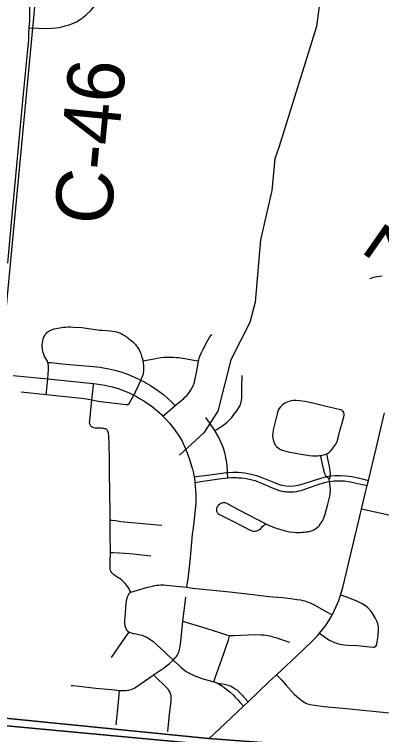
# Model space of a CAD drawing. Extents: x 0 to 34, y 0 to 22.
# Drawn here: x 22.884 to 23.251, y 14.925 to 15.645 of the extents above; entities that cross this region are included whole.
import ezdxf

# ---------------------------------------------------------------- set-up
doc = ezdxf.new("R2010")
doc.units = 0
for name, color, linetype in [('GM_X_City_Street', 7, 'Continuous'), ('GM_X_County_Road', 7, 'Continuous'), ('GM_X_County_Road_Text', 7, 'Continuous'), ('GM_X_Minor_River', 7, 'Continuous'), ('GM_X_Section', 7, 'Continuous'), ('GM_X_Township_Road', 7, 'Continuous'), ('SH_Border', 7, 'Continuous')]:
    doc.layers.add(name, color=color, linetype=linetype)

msp = doc.modelspace()

# ---------------------------------------------------------------- linework, layer by layer
at = {"layer": 'GM_X_City_Street'}
for p, q in [((22.89059, 15.26813), (22.91581, 15.26543)), ((23.19877, 15.17844), (23.19831, 15.18065)), ((23.0832, 14.97792), (23.0861, 14.97706))]:
    msp.add_line(p, q, dxfattribs=at)
for points in [[(22.91735, 15.29732), (22.91685, 15.29851), (22.91479, 15.30222), (22.91417, 15.30347), (22.91335, 15.30539), (22.91271, 15.30722), (22.91236, 15.30861), (22.91203, 15.31023), (22.9119, 15.31123), (22.9118, 15.31314), (22.91184, 15.31506), (22.91198, 15.31712), (22.91224, 15.31904), (22.91274, 15.32094), (22.91343, 15.32281), (22.91389, 15.32371), (22.91482, 15.32528), (22.91541, 15.32608), (22.916, 15.3268), (22.91673, 15.32749), (22.91746, 15.32805), (22.91833, 15.3287), (22.91927, 15.32924), (22.92084, 15.32994), (22.92187, 15.33034), (22.92288, 15.33069), (22.92353, 15.33088), (22.92558, 15.33137), (22.93115, 15.33237), (22.93253, 15.33253), (22.93405, 15.33266), (22.93524, 15.33275), (22.9374, 15.33284), (22.94042, 15.33286), (22.94255, 15.33279), (22.9512, 15.33216), (22.95793, 15.33131), (22.96921, 15.32978), (22.97153, 15.32954), (22.97996, 15.32888), (22.98168, 15.32867), (22.98424, 15.32826), (22.98596, 15.32786), (22.98797, 15.32729), (22.98918, 15.32683), (22.99046, 15.32626), (22.99194, 15.32547), (22.99343, 15.32457), (22.99458, 15.32383), (22.99525, 15.32338), (22.99644, 15.32254), (22.99745, 15.32181), (22.99924, 15.32045), (23.00028, 15.31961), (23.00218, 15.31795), (23.00357, 15.31661), (23.00474, 15.31534), (23.00605, 15.31373), (23.00676, 15.31277), (23.00789, 15.31109), (23.0086, 15.30985), (23.00966, 15.30771), (23.01022, 15.30628), (23.01104, 15.30376), (23.01209, 15.29997), (23.01227, 15.29884)], [(23.06785, 15.29885), (23.06812, 15.30006), (23.06887, 15.30269), (23.0695, 15.3044), (23.07039, 15.3065), (23.07184, 15.30946), (23.07637, 15.31815), (23.07919, 15.32302), (23.08069, 15.32512), (23.08113, 15.32562)], [(23.01227, 15.29884), (23.01772, 15.29995), (23.02339, 15.30112), (23.02653, 15.30166), (23.03011, 15.30216), (23.03336, 15.3025), (23.03586, 15.30267), (23.03895, 15.30274), (23.0428, 15.30267), (23.0454, 15.30246), (23.04814, 15.30218), (23.05037, 15.30185), (23.06301, 15.29968), (23.06785, 15.29885)], [(22.91719, 15.28104), (22.91785, 15.29033), (22.91792, 15.2915), (22.91796, 15.29337), (22.91792, 15.29448), (22.91784, 15.29547), (22.91769, 15.29618), (22.91735, 15.29732)], [(22.91735, 15.29732), (22.91833, 15.29728), (22.9203, 15.29717), (22.93515, 15.29549), (22.96294, 15.29316), (22.96977, 15.29252), (22.97462, 15.29178), (22.97673, 15.29136), (22.98303, 15.2899), (22.98543, 15.28927), (22.99111, 15.2876), (22.9934, 15.28684), (22.99774, 15.28523), (22.99979, 15.28439), (23.00763, 15.28096), (23.00909, 15.28026), (23.01016, 15.27971)], [(23.01227, 15.29884), (23.01265, 15.29664), (23.01286, 15.29463), (23.01293, 15.29339), (23.01293, 15.29098), (23.01283, 15.28904), (23.01259, 15.28695), (23.01239, 15.28582), (23.01194, 15.2841), (23.01153, 15.28285), (23.01129, 15.28224), (23.0107, 15.28087), (23.01016, 15.27971)], [(23.04455, 15.25417), (23.05299, 15.26135), (23.05461, 15.26289), (23.05645, 15.2648), (23.05768, 15.26623), (23.0587, 15.26754), (23.05985, 15.2692), (23.06061, 15.27046), (23.06161, 15.27235), (23.06267, 15.27481), (23.06372, 15.27778), (23.06426, 15.27963), (23.0656, 15.28526), (23.06689, 15.29252), (23.06785, 15.29885)], [(22.88285, 15.28427), (22.91719, 15.28104), (22.94959, 15.27764), (22.96308, 15.27617), (22.96568, 15.27588), (22.97433, 15.27453), (22.98167, 15.27293), (22.9877, 15.27121), (22.99362, 15.2691), (22.99855, 15.26695), (23.00057, 15.26597), (23.00315, 15.26464), (23.00599, 15.26317), (23.00904, 15.26145), (23.01313, 15.25903), (23.01568, 15.25734), (23.02008, 15.25425), (23.02394, 15.2513), (23.02622, 15.24938), (23.03083, 15.24524), (23.0323, 15.24374), (23.03565, 15.24032), (23.0389, 15.23657), (23.04133, 15.2336), (23.04393, 15.23021), (23.04599, 15.22728), (23.04769, 15.22474), (23.04944, 15.22192), (23.0514, 15.21853), (23.0539, 15.21346), (23.05653, 15.20709), (23.05924, 15.19943), (23.06127, 15.19258), (23.06182, 15.1906), (23.06246, 15.18799), (23.06318, 15.1847), (23.0635, 15.18299), (23.06387, 15.18105), (23.06441, 15.17747)], [(22.91581, 15.26543), (22.91602, 15.26782), (22.91719, 15.28104)], [(23.084, 15.22933), (23.08605, 15.23047), (23.08793, 15.23152), (23.0892, 15.2323), (23.09116, 15.2336), (23.09475, 15.23633), (23.09627, 15.23759), (23.09766, 15.23887), (23.09917, 15.24041), (23.10096, 15.24243), (23.10248, 15.24427), (23.10481, 15.24727), (23.10608, 15.24901), (23.10773, 15.25153), (23.1087, 15.2532), (23.10927, 15.25436), (23.10983, 15.25571), (23.11015, 15.25667), (23.11034, 15.25741), (23.11057, 15.25853), (23.11069, 15.25924), (23.11094, 15.26212), (23.11123, 15.2724), (23.11155, 15.28423)], [(22.96138, 15.2599), (22.96199, 15.26565), (22.96285, 15.2743), (22.96308, 15.27617)], [(23.01016, 15.27971), (23.00458, 15.26772), (23.00315, 15.26464)], [(23.01016, 15.27971), (23.01312, 15.27818), (23.01531, 15.27693), (23.01984, 15.2742), (23.02811, 15.26865), (23.03313, 15.26493), (23.03696, 15.26168), (23.04096, 15.25792), (23.04263, 15.25617), (23.04455, 15.25417)], [(22.91581, 15.26543), (22.95097, 15.26167), (22.95376, 15.26132), (22.95611, 15.2609), (22.96138, 15.2599)], [(22.95915, 15.23884), (22.96033, 15.2499), (22.96138, 15.2599)], [(22.96138, 15.2599), (22.96596, 15.25903), (22.96781, 15.25873), (22.96984, 15.25846), (22.99571, 15.2552), (22.99665, 15.25525), (22.99736, 15.25547), (22.99844, 15.25635), (23.00315, 15.26464)], [(23.19598, 15.20606), (23.197, 15.20658), (23.19763, 15.20693), (23.19858, 15.20762), (23.19932, 15.20836), (23.19993, 15.2091), (23.20307, 15.21296), (23.2048, 15.21553), (23.20617, 15.21832), (23.2073, 15.22187), (23.2091, 15.2291), (23.21078, 15.23572), (23.21282, 15.24289), (23.21319, 15.24472), (23.21319, 15.24596), (23.21284, 15.24717), (23.2122, 15.24829), (23.21132, 15.24922), (23.2108, 15.2496), (23.20965, 15.25002), (23.19278, 15.25411), (23.18191, 15.25663), (23.17401, 15.25818), (23.16914, 15.25914), (23.16542, 15.2594), (23.16232, 15.25927), (23.15926, 15.25873), (23.1569, 15.25796), (23.15412, 15.25659), (23.15156, 15.25483), (23.14973, 15.25315), (23.14821, 15.25118), (23.14737, 15.24952), (23.14638, 15.24594), (23.14277, 15.23147), (23.14197, 15.22719), (23.14182, 15.22471), (23.14205, 15.22161), (23.14269, 15.21856), (23.14355, 15.21624), (23.14452, 15.21465), (23.14573, 15.21325), (23.14765, 15.21167), (23.1498, 15.21043), (23.15269, 15.2093), (23.15749, 15.20801), (23.17031, 15.20565), (23.17827, 15.20431), (23.18198, 15.20398), (23.18519, 15.20394), (23.18639, 15.20398), (23.1885, 15.20417), (23.18986, 15.20437)], [(23.0323, 15.24374), (23.03418, 15.24533), (23.04455, 15.25417)], [(22.97953, 15.13978), (22.97945, 15.14593), (22.9792, 15.16766), (22.97904, 15.18693), (22.97891, 15.1987), (22.97851, 15.21811), (22.97842, 15.22057), (22.9783, 15.22308), (22.97817, 15.2247), (22.97804, 15.22592), (22.97794, 15.22662), (22.97763, 15.22781), (22.97725, 15.22874), (22.97689, 15.22932), (22.97594, 15.2303), (22.97488, 15.23084), (22.97423, 15.23106), (22.97331, 15.23128), (22.97205, 15.23145), (22.97065, 15.23155), (22.96825, 15.23158), (22.96452, 15.23181), (22.96327, 15.232), (22.96228, 15.23224), (22.96158, 15.23256), (22.96102, 15.23292), (22.96041, 15.23353), (22.9599, 15.23429), (22.95962, 15.23485), (22.95926, 15.23608), (22.95912, 15.23744), (22.95915, 15.23884)], [(23.09716, 15.18204), (23.0968, 15.18734), (23.09629, 15.19485), (23.09576, 15.19888), (23.0952, 15.20216), (23.09472, 15.20449), (23.0941, 15.20703), (23.09268, 15.21182), (23.0911, 15.21579), (23.08992, 15.21855), (23.08768, 15.22316), (23.08454, 15.22851), (23.084, 15.22933), (23.0798, 15.2358), (23.07507, 15.24235)], [(23.18986, 15.20437), (23.19052, 15.20446), (23.19146, 15.20464), (23.19271, 15.20494), (23.19391, 15.20529), (23.19598, 15.20606)], [(23.19552, 15.18323), (23.19475, 15.18445), (23.19419, 15.18569), (23.1937, 15.18714), (23.19326, 15.18872), (23.19278, 15.19106), (23.19038, 15.20184), (23.19003, 15.20354), (23.18986, 15.20437)], [(23.19958, 15.18394), (23.19969, 15.18509), (23.19963, 15.1867), (23.19942, 15.18837), (23.19884, 15.19156), (23.19657, 15.20278), (23.19621, 15.20477), (23.19598, 15.20606)], [(23.0635, 15.18299), (23.06548, 15.18327), (23.06759, 15.18358), (23.07419, 15.18442), (23.0865, 15.18613), (23.09575, 15.18728), (23.0968, 15.18734), (23.10196, 15.18764), (23.10755, 15.18754), (23.11372, 15.18686), (23.12044, 15.18558), (23.12586, 15.1842), (23.13117, 15.18243), (23.14088, 15.1783), (23.14668, 15.17602), (23.15085, 15.17479), (23.15511, 15.174), (23.15883, 15.17373), (23.16317, 15.17392), (23.16746, 15.17465), (23.17226, 15.17592), (23.18053, 15.17866), (23.18995, 15.1818), (23.19474, 15.18309), (23.19552, 15.18323), (23.19958, 15.18394), (23.20393, 15.18441), (23.2095, 15.18448), (23.21506, 15.18414), (23.22118, 15.1833), (23.22845, 15.18177), (23.23122, 15.18106), (23.2375, 15.17945)], [(23.06441, 15.17747), (23.07222, 15.17866), (23.09075, 15.18133), (23.09453, 15.18178), (23.09716, 15.18204), (23.10069, 15.18223), (23.1039, 15.18226), (23.10591, 15.18227), (23.10791, 15.18217), (23.11091, 15.18191), (23.11353, 15.18157), (23.11707, 15.18093), (23.12123, 15.17993), (23.12393, 15.1792), (23.12671, 15.17831), (23.12836, 15.17767), (23.13547, 15.17455), (23.14233, 15.17162), (23.1476, 15.16975), (23.15111, 15.16881), (23.15261, 15.16849), (23.15419, 15.16823), (23.15575, 15.16805), (23.15828, 15.1679), (23.15943, 15.16791), (23.16173, 15.16799), (23.16317, 15.16814), (23.16571, 15.16848), (23.16785, 15.16891), (23.17029, 15.1695), (23.17244, 15.17013), (23.17849, 15.17227), (23.18728, 15.17539), (23.19369, 15.17729), (23.19614, 15.17795), (23.19877, 15.17844), (23.20295, 15.17894), (23.20528, 15.17907), (23.20805, 15.17911), (23.21074, 15.17907), (23.21345, 15.17884), (23.21739, 15.17834), (23.21961, 15.17796), (23.22381, 15.17709), (23.23004, 15.17577), (23.23626, 15.17446)], [(23.19831, 15.18065), (23.19648, 15.18223), (23.19601, 15.18267), (23.19552, 15.18323)], [(23.19831, 15.18065), (23.19916, 15.18246), (23.19958, 15.18394)], [(23.05623, 15.07258), (23.05657, 15.0752), (23.05734, 15.08106), (23.05878, 15.09266), (23.05947, 15.09883), (23.06041, 15.10993), (23.06185, 15.12529), (23.06267, 15.132), (23.06342, 15.13787), (23.06415, 15.14368), (23.06511, 15.15337), (23.06541, 15.15706), (23.0655, 15.15957), (23.06551, 15.16351), (23.06542, 15.16629), (23.06522, 15.16928), (23.06441, 15.17747)], [(23.13519, 15.13535), (23.13427, 15.1351), (23.13363, 15.13481), (23.13255, 15.134), (23.13088, 15.13251), (23.12897, 15.13046), (23.1281, 15.12972), (23.12728, 15.12918), (23.12662, 15.12885), (23.12577, 15.12857), (23.12431, 15.12834), (23.12336, 15.12837), (23.12268, 15.12848), (23.1215, 15.1288), (23.12062, 15.12909), (23.11853, 15.13003), (23.11769, 15.13046), (23.11484, 15.132), (23.10041, 15.13933), (23.09056, 15.1442), (23.08919, 15.14495), (23.08851, 15.14539), (23.08793, 15.1458), (23.08729, 15.14634), (23.08679, 15.14697), (23.08643, 15.14762), (23.08613, 15.14844), (23.08596, 15.14951), (23.08593, 15.1502), (23.08599, 15.15086), (23.0862, 15.15182), (23.08647, 15.15255), (23.08679, 15.15323), (23.08733, 15.15402), (23.08802, 15.15489), (23.08862, 15.15552), (23.08976, 15.15641), (23.09085, 15.15703), (23.09198, 15.15731), (23.09298, 15.15735), (23.09362, 15.1573), (23.09426, 15.15722), (23.09512, 15.15704), (23.0966, 15.15647), (23.09777, 15.15583), (23.10084, 15.15406), (23.10683, 15.15065), (23.11789, 15.14491), (23.12663, 15.14025), (23.13491, 15.13585), (23.14008, 15.13358), (23.14547, 15.13164), (23.14883, 15.13059), (23.15325, 15.12933), (23.15876, 15.12812), (23.16276, 15.12761), (23.16503, 15.12744), (23.16727, 15.12742), (23.16964, 15.12749), (23.17145, 15.12759), (23.17319, 15.12771), (23.17495, 15.12786), (23.17651, 15.12806), (23.1777, 15.12824), (23.17872, 15.12843), (23.17953, 15.12862), (23.18125, 15.12919), (23.18232, 15.12964), (23.18312, 15.13006), (23.18404, 15.13057), (23.18469, 15.13098), (23.18545, 15.13152), (23.18647, 15.13234), (23.18717, 15.13298), (23.1878, 15.13363), (23.18854, 15.13449), (23.1891, 15.1352), (23.19025, 15.13685), (23.1912, 15.13834), (23.1919, 15.13965), (23.19258, 15.14098), (23.19301, 15.14191), (23.19345, 15.14304), (23.19397, 15.14453), (23.19478, 15.14716), (23.19692, 15.15566), (23.1988, 15.16375), (23.19918, 15.16553), (23.19942, 15.16696), (23.1996, 15.16854), (23.1996, 15.17079), (23.19877, 15.17844)], [(23.27293, 15.14127), (23.24437, 15.14754), (23.23061, 15.15057)], [(22.97977, 15.1074), (22.97973, 15.12668), (22.97953, 15.13978)], [(22.97953, 15.13978), (22.98024, 15.13976), (22.98152, 15.13972), (22.98499, 15.13926), (22.9904, 15.13845), (23.00482, 15.13692), (23.02698, 15.13489), (23.03129, 15.13452)], [(23.00026, 15.06779), (22.99938, 15.0695), (22.99885, 15.07046), (22.99852, 15.07104), (22.9979, 15.07202), (22.99695, 15.07344), (22.99629, 15.07433), (22.99468, 15.0763), (22.99392, 15.07712), (22.9923, 15.07872), (22.99126, 15.07962), (22.98956, 15.08091), (22.98824, 15.08181), (22.98415, 15.08433), (22.98325, 15.08495), (22.98247, 15.08558), (22.98171, 15.08631), (22.98113, 15.08697), (22.98068, 15.08767), (22.98017, 15.08874), (22.97996, 15.08933), (22.97963, 15.09066), (22.97947, 15.09268), (22.97952, 15.09532), (22.97961, 15.09845), (22.97977, 15.1074)], [(22.97977, 15.1074), (22.98244, 15.10732), (22.98901, 15.10709), (22.9944, 15.10673), (23.00245, 15.10614), (23.02025, 15.10414)], [(23.00026, 15.06779), (23.00361, 15.06882), (23.01588, 15.07231), (23.0219, 15.07383), (23.02416, 15.07429), (23.02602, 15.07458), (23.02812, 15.07481), (23.02998, 15.07488), (23.03307, 15.07486), (23.03543, 15.07471), (23.04943, 15.07347), (23.05623, 15.07258), (23.06179, 15.07185), (23.0958, 15.06819), (23.11376, 15.06629), (23.13848, 15.06346), (23.14219, 15.06309), (23.15214, 15.06225), (23.16017, 15.06126), (23.16584, 15.06047), (23.16953, 15.05992), (23.17199, 15.05943), (23.17402, 15.05894), (23.17549, 15.05845), (23.17796, 15.05752), (23.17924, 15.05688), (23.18277, 15.0553), (23.18391, 15.05472), (23.18879, 15.05202), (23.19637, 15.04771), (23.20134, 15.04489)], [(23.00026, 15.06779), (22.99946, 15.06723), (22.99898, 15.06678), (22.99837, 15.06609), (22.99799, 15.06557), (22.99747, 15.06473), (22.99717, 15.06416), (22.99676, 15.0633), (22.99648, 15.06263), (22.99611, 15.06145), (22.99585, 15.06043), (22.99553, 15.05873), (22.99532, 15.0571), (22.99444, 15.04681), (22.99394, 15.03887), (22.99392, 15.03723), (22.99397, 15.03621), (22.99415, 15.03477), (22.99429, 15.03406), (22.9946, 15.03295), (22.99493, 15.03207), (22.9955, 15.03096), (22.99599, 15.03017), (22.9966, 15.02942), (22.99731, 15.02871), (22.99854, 15.02782)], [(23.18855, 15.02655), (23.19477, 15.02224), (23.19784, 15.02012), (23.20113, 15.01835), (23.20458, 15.01694), (23.20668, 15.01621), (23.20894, 15.01559), (23.21091, 15.01525), (23.21305, 15.01498), (23.21739, 15.01465), (23.2261, 15.01442), (23.24237, 15.01275), (23.24326, 15.01275), (23.24399, 15.01291), (23.2449, 15.01356), (23.24574, 15.01535), (23.24627, 15.01798), (23.24711, 15.02415), (23.24759, 15.03034), (23.24752, 15.03283), (23.24728, 15.03463), (23.24696, 15.03588), (23.24597, 15.03883), (23.24428, 15.04215), (23.24134, 15.04692), (23.24025, 15.04839), (23.23945, 15.04939), (23.23809, 15.05085), (23.23684, 15.05205), (23.23443, 15.05401), (23.23284, 15.05508), (23.23126, 15.05598), (23.22916, 15.05712), (23.22511, 15.05899), (23.2194, 15.06147), (23.21527, 15.06287), (23.20971, 15.06478)], [(23.05225, 15.03864), (23.05279, 15.04371), (23.05507, 15.06276)], [(23.04255, 14.99971), (23.04458, 15.00193), (23.04572, 15.00337), (23.04636, 15.0043), (23.04747, 15.00629), (23.04798, 15.00743), (23.0484, 15.00863), (23.04884, 15.01026), (23.04916, 15.01183), (23.04975, 15.01565), (23.05115, 15.02828), (23.05225, 15.03864)], [(23.05225, 15.03864), (23.05507, 15.03778), (23.07096, 15.03301), (23.07629, 15.03134), (23.08867, 15.02733), (23.09561, 15.02502), (23.09736, 15.02457), (23.09906, 15.02428)], [(22.98091, 15.00245), (22.98761, 15.01204), (22.99571, 15.02364), (22.99783, 15.02677), (22.99854, 15.02782)], [(22.99854, 15.02782), (22.9994, 15.02736), (23.00055, 15.02692), (23.00145, 15.02666), (23.00269, 15.02643), (23.0039, 15.02623), (23.00565, 15.02594), (23.00681, 15.02571), (23.00956, 15.02507), (23.01109, 15.02464), (23.01235, 15.02423), (23.01427, 15.02347), (23.01556, 15.02288), (23.01734, 15.02196), (23.01874, 15.02115), (23.02016, 15.02018), (23.02242, 15.01838), (23.02606, 15.01516), (23.0338, 15.008), (23.04255, 14.99971)], [(23.0832, 14.97792), (23.0839, 14.98007), (23.08519, 14.98404), (23.09071, 14.99976), (23.09777, 15.02017), (23.09854, 15.02255), (23.09906, 15.02428)], [(23.09906, 15.02428), (23.10089, 15.0242), (23.10287, 15.02426), (23.11743, 15.0251), (23.12513, 15.0252), (23.1303, 15.02508), (23.13267, 15.02492), (23.13505, 15.02465), (23.13721, 15.02431), (23.14041, 15.02365), (23.14214, 15.02319), (23.14597, 15.02206), (23.14864, 15.02119), (23.1588, 15.01771)], [(23.02297, 14.98502), (23.0327, 14.99165), (23.03891, 14.99651), (23.04255, 14.99971)], [(23.04255, 14.99971), (23.04802, 14.99454), (23.05039, 14.99243), (23.05207, 14.99105), (23.05425, 14.9894), (23.0556, 14.98847), (23.05809, 14.98693), (23.05929, 14.98627), (23.06211, 14.98489), (23.06401, 14.98406), (23.06688, 14.98296), (23.07121, 14.98149), (23.0832, 14.97792)], [(22.98885, 14.96953), (22.98972, 14.96945), (22.99194, 14.96936), (22.99404, 14.96936), (22.99532, 14.96944), (22.99674, 14.96958), (22.99801, 14.96978), (22.99931, 14.97005), (23.00068, 14.97046), (23.00216, 14.97103), (23.00379, 14.97184), (23.00558, 14.97287), (23.00633, 14.97336), (23.00952, 14.97556), (23.02245, 14.98466), (23.02297, 14.98502)], [(23.03726, 14.92824), (23.03897, 14.94577), (23.04038, 14.9585), (23.04048, 14.96011), (23.04051, 14.96172), (23.04045, 14.96323), (23.04038, 14.96421), (23.04014, 14.96537), (23.03989, 14.96613), (23.03948, 14.9672), (23.03905, 14.9681), (23.03852, 14.96909), (23.03788, 14.97006), (23.0374, 14.97069), (23.03655, 14.9717), (23.03532, 14.97304), (23.02497, 14.98307), (23.02297, 14.98502)], [(23.14584, 14.98515), (23.15088, 14.97957), (23.15508, 14.97492), (23.16347, 14.96581), (23.16795, 14.96163), (23.17133, 14.95904), (23.17387, 14.95746), (23.17509, 14.95683), (23.17653, 14.95617), (23.17792, 14.95568), (23.17943, 14.95535), (23.18362, 14.95455), (23.19346, 14.95343), (23.21201, 14.95159), (23.2584, 14.94701)], [(22.94074, 14.97446), (22.94259, 14.97429), (22.9654, 14.97175), (22.98084, 14.97025), (22.98885, 14.96953)], [(23.0861, 14.97706), (23.09013, 14.97473), (23.09177, 14.97375), (23.09354, 14.9725), (23.09925, 14.96789), (23.1027, 14.96469), (23.10421, 14.96315), (23.10718, 14.95991), (23.10939, 14.95746), (23.11282, 14.95365)], [(23.0861, 14.97706), (23.09346, 14.97577), (23.09518, 14.97539), (23.09659, 14.97499), (23.09813, 14.97449), (23.09945, 14.97392), (23.10082, 14.97321), (23.1024, 14.97234), (23.10431, 14.97114), (23.10564, 14.97022), (23.10672, 14.96937), (23.10818, 14.9681), (23.1102, 14.96613), (23.11179, 14.96433), (23.11281, 14.96311), (23.11405, 14.96165), (23.11726, 14.95789)], [(22.9857, 14.93512), (22.98778, 14.9577), (22.98885, 14.96953)]]:
    msp.add_lwpolyline(points, dxfattribs=at)
at = {"layer": 'GM_X_County_Road'}
msp.add_lwpolyline([(22.51637, 15.98566), (22.51637, 14.96793), (22.83652, 14.9377), (22.93242, 15.94904), (22.91541, 15.95085)], close=True, dxfattribs=at)
for points in [[(22.89882, 15.63186), (22.89927, 15.63883), (22.89946, 15.64944), (22.89911, 15.65695), (22.89825, 15.66441), (22.89689, 15.67241), (22.89508, 15.68033), (22.89304, 15.68753), (22.88985, 15.69698), (22.88058, 15.72135), (22.87761, 15.73013), (22.87512, 15.73903), (22.87355, 15.74688), (22.87255, 15.7542), (22.87196, 15.76218), (22.87184, 15.77019), (22.87217, 15.77883), (22.87302, 15.78932), (22.87616, 15.82018), (22.88175, 15.87826), (22.88613, 15.92148), (22.8869, 15.93202), (22.88867, 15.94803)], [(22.87737, 15.39678), (22.8793, 15.41847), (22.88192, 15.44819), (22.88393, 15.46921), (22.8924, 15.55893), (22.89821, 15.6202), (22.89827, 15.62331), (22.89848, 15.6264), (22.89882, 15.63186)], [(23.23626, 15.17446), (23.2375, 15.17945), (23.24531, 15.21123), (23.25336, 15.24573), (23.25366, 15.24697)], [(23.23061, 15.15057), (23.23492, 15.16899), (23.23626, 15.17446)], [(23.20971, 15.06478), (23.21187, 15.07231), (23.21604, 15.08913), (23.22004, 15.10608), (23.22599, 15.13085), (23.23061, 15.15057)], [(23.20134, 15.04489), (23.20196, 15.04605), (23.2054, 15.0532), (23.20789, 15.05943), (23.20971, 15.06478)], [(23.18855, 15.02655), (23.19169, 15.03024), (23.19364, 15.0328), (23.19534, 15.03511), (23.19835, 15.03969), (23.20032, 15.04299), (23.20134, 15.04489)], [(23.14584, 14.98515), (23.16526, 15.00351), (23.18101, 15.01844), (23.18654, 15.02419), (23.18855, 15.02655)], [(23.11282, 14.95365), (23.11726, 14.95789), (23.13816, 14.97788), (23.14584, 14.98515)], [(23.07814, 14.92095), (23.08359, 14.92619), (23.10087, 14.94225), (23.11282, 14.95365)]]:
    msp.add_lwpolyline(points, dxfattribs=at)
at = {"layer": 'GM_X_Minor_River'}
msp.add_lwpolyline([(23.19408, 15.69672), (23.18559, 15.63311), (23.14789, 15.51238), (23.14387, 15.50107), (23.14096, 15.46925), (23.12973, 15.42012), (23.1243, 15.35759), (23.11896, 15.3372), (23.10001, 15.3), (23.08722, 15.24863), (23.07313, 15.2269), (23.04878, 15.20462)], dxfattribs=at)
at = {"layer": 'GM_X_Section'}
for points in [[(22.93242, 15.94904), (23.88549, 15.85603), (23.90516, 15.85455), (23.81234, 14.84657), (22.83652, 14.9377)], [(23.81234, 14.84657), (23.73099, 13.84446), (22.74129, 13.94338), (22.83652, 14.9377)]]:
    msp.add_lwpolyline(points, close=True, dxfattribs=at)
at = {"layer": 'GM_X_Township_Road'}
for points in [[(22.89882, 15.63186), (22.90798, 15.63159), (22.91503, 15.63139), (22.92178, 15.63144), (22.92526, 15.6318), (22.92866, 15.63233), (22.93141, 15.63291), (22.93478, 15.63377), (22.93764, 15.63464), (22.94133, 15.63589), (22.94366, 15.63692), (22.94591, 15.63801), (22.95077, 15.64097), (22.95573, 15.64488), (22.96025, 15.64928), (22.96799, 15.65824), (22.98417, 15.67709), (22.99707, 15.69221), (23.00016, 15.69583)], [(23.23901, 15.38133), (23.24127, 15.38212), (23.24303, 15.38264), (23.24611, 15.38333), (23.24843, 15.38373), (23.25107, 15.38396)]]:
    msp.add_lwpolyline(points, dxfattribs=at)
at = {"layer": 'SH_Border'}
for points in [[(22.51637, 19.03183), (22.51637, 14.97433), (22.53748, 14.97157), (22.5519, 14.96981), (22.58542, 14.9669), (22.62619, 14.96271), (22.67598, 14.95801), (22.69418, 14.9563), (22.71892, 14.95402), (22.74245, 14.95174), (22.74837, 14.95098), (22.75142, 14.95053), (22.75414, 14.94979), (22.75606, 14.949), (22.75808, 14.9478), (22.82376, 14.94586), (22.83456, 14.94555), (23.07791, 14.92148), (23.52854, 14.88774), (23.81459, 14.86633)], [(23.81459, 14.86633), (23.52854, 14.88774), (23.07791, 14.92148), (22.83456, 14.94555), (22.82376, 14.94586), (22.75808, 14.9478), (22.75606, 14.949), (22.75414, 14.94979), (22.75142, 14.95053), (22.74837, 14.95098), (22.74245, 14.95174), (22.71892, 14.95402), (22.69418, 14.9563), (22.67598, 14.95801), (22.62619, 14.96271), (22.58542, 14.9669), (22.5519, 14.96981), (22.53748, 14.97157), (22.51637, 14.97433), (22.51637, 13.46181)]]:
    msp.add_lwpolyline(points, dxfattribs=at)

# ---------------------------------------------------------------- texts
at = {"layer": 'GM_X_County_Road_Text'}
for s, height, rotation, p in [('C-46', 0.056818, 84.52725, (22.97979, 15.43339)), ('Z', 0.05682, 55.10277, (23.27666, 15.36862))]:
    msp.add_text(s, height=height, rotation=rotation, dxfattribs=at).set_placement(p)

doc.saveas('drawing.dxf')
